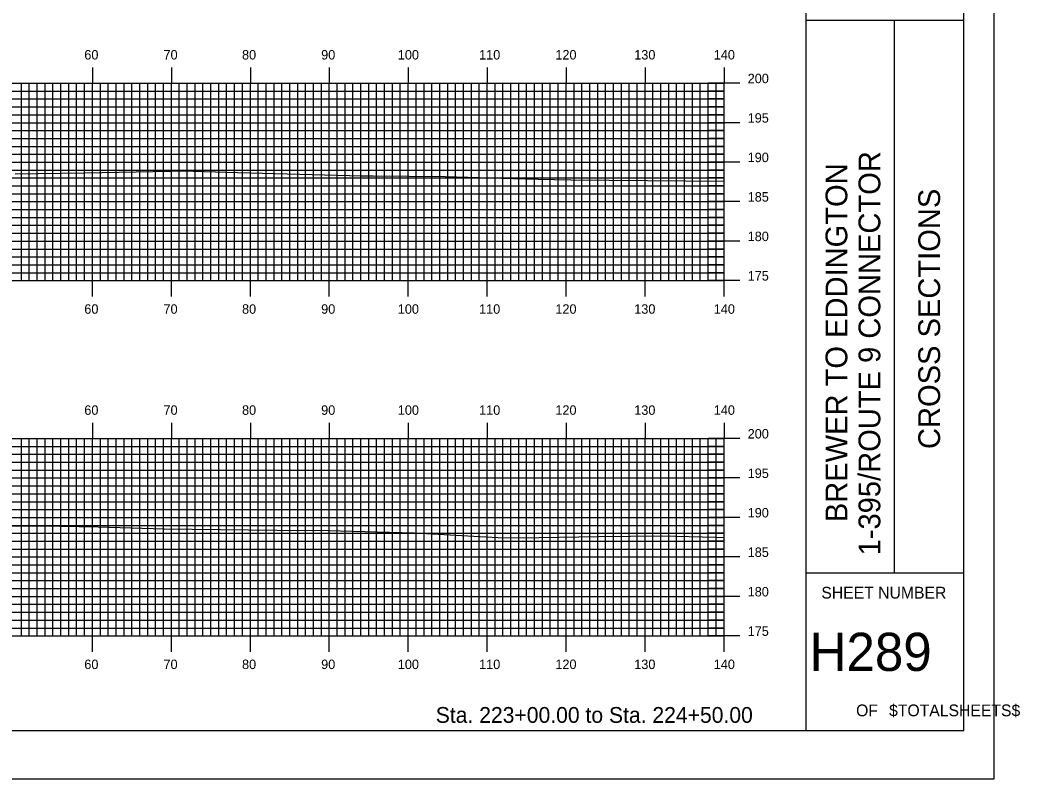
# Model space of a CAD drawing. Extents: x 1797994 to 1798337, y 442591 to 442811.
# Drawn here: x 1798210.8 to 1798337.5, y 442590.5 to 442686.7 of the extents above; entities that cross this region are included whole.
import ezdxf

# ---------------------------------------------------------------- set-up
doc = ezdxf.new("R2010")
doc.units = 0
for name, color, linetype in [('BORDER', 7, 'Continuous'), ('H_V ANNOTATION', 7, 'Continuous'), ('MAJOR', 7, 'Continuous'), ('MINOR', 7, 'Continuous'), ('PLOT BOUNDARY', 7, 'Continuous'), ('S_Roadway_Centerline', 7, 'Continuous')]:
    doc.layers.add(name, color=color, linetype=linetype)

msp = doc.modelspace()

# ---------------------------------------------------------------- linework, layer by layer
at = {"layer": 'BORDER'}
for p, q in [((1798310.36, 442596.67), (1798310.36, 442806.67)), ((1798310.36, 442686.67), (1798330.36, 442686.67)), ((1798321.54, 442616.67), (1798321.54, 442686.67)), ((1798310.36, 442616.67), (1798330.36, 442616.67))]:
    msp.add_line(p, q, dxfattribs=at)
msp.add_lwpolyline([(1798010.36, 442596.67), (1798330.36, 442596.67), (1798330.36, 442806.67), (1798010.36, 442806.67)], close=True, dxfattribs=at)
at = {"layer": 'MAJOR'}
for p, q in [((1798219.96, 442680.67), (1798219.96, 442678.67)), ((1798229.96, 442680.67), (1798229.96, 442678.67)), ((1798239.96, 442680.67), (1798239.96, 442678.67)), ((1798249.96, 442680.67), (1798249.96, 442678.67)), ((1798259.96, 442680.67), (1798259.96, 442678.67)), ((1798269.96, 442680.67), (1798269.96, 442678.67)), ((1798279.96, 442680.67), (1798279.96, 442678.67)), ((1798289.96, 442680.67), (1798289.96, 442678.67)), ((1798299.96, 442680.67), (1798299.96, 442678.67)), ((1798019.96, 442678.67), (1798299.96, 442678.67)), ((1798019.96, 442678.67), (1798299.96, 442678.67)), ((1798219.96, 442653.67), (1798219.96, 442678.67)), ((1798229.96, 442653.67), (1798229.96, 442678.67)), ((1798239.96, 442653.67), (1798239.96, 442678.67)), ((1798249.96, 442653.67), (1798249.96, 442678.67)), ((1798259.96, 442653.67), (1798259.96, 442678.67)), ((1798269.96, 442653.67), (1798269.96, 442678.67)), ((1798279.96, 442653.67), (1798279.96, 442678.67)), ((1798289.96, 442653.67), (1798289.96, 442678.67)), ((1798301.96, 442678.67), (1798297.95, 442678.67)), ((1798299.96, 442653.67), (1798299.96, 442678.67)), ((1798299.96, 442653.67), (1798299.96, 442678.67)), ((1798019.96, 442673.67), (1798299.96, 442673.67)), ((1798301.96, 442673.67), (1798297.95, 442673.67)), ((1798019.96, 442668.67), (1798299.96, 442668.67)), ((1798301.96, 442668.67), (1798297.95, 442668.67)), ((1798019.96, 442663.67), (1798299.96, 442663.67)), ((1798301.96, 442663.67), (1798297.95, 442663.67)), ((1798019.96, 442658.67), (1798299.96, 442658.67)), ((1798301.96, 442658.67), (1798297.95, 442658.67)), ((1798019.96, 442653.67), (1798299.96, 442653.67)), ((1798019.96, 442653.67), (1798299.96, 442653.67)), ((1798219.96, 442651.66), (1798219.96, 442653.67)), ((1798229.96, 442651.66), (1798229.96, 442653.67)), ((1798239.96, 442651.66), (1798239.96, 442653.67)), ((1798249.96, 442651.66), (1798249.96, 442653.67)), ((1798259.96, 442651.66), (1798259.96, 442653.67)), ((1798269.96, 442651.66), (1798269.96, 442653.67)), ((1798279.96, 442651.66), (1798279.96, 442653.67)), ((1798289.96, 442651.66), (1798289.96, 442653.67)), ((1798301.96, 442653.67), (1798297.95, 442653.67)), ((1798299.96, 442651.66), (1798299.96, 442653.67)), ((1798219.96, 442635.67), (1798219.96, 442633.67)), ((1798229.96, 442635.67), (1798229.96, 442633.67)), ((1798239.96, 442635.67), (1798239.96, 442633.67)), ((1798249.96, 442635.67), (1798249.96, 442633.67)), ((1798259.96, 442635.67), (1798259.96, 442633.67)), ((1798269.96, 442635.67), (1798269.96, 442633.67)), ((1798279.96, 442635.67), (1798279.96, 442633.67)), ((1798289.96, 442635.67), (1798289.96, 442633.67)), ((1798299.96, 442635.67), (1798299.96, 442633.67)), ((1798019.96, 442633.67), (1798299.96, 442633.67)), ((1798019.96, 442633.67), (1798299.96, 442633.67)), ((1798219.96, 442608.67), (1798219.96, 442633.67)), ((1798229.96, 442608.67), (1798229.96, 442633.67)), ((1798239.96, 442608.67), (1798239.96, 442633.67)), ((1798249.96, 442608.67), (1798249.96, 442633.67)), ((1798259.96, 442608.67), (1798259.96, 442633.67)), ((1798269.96, 442608.67), (1798269.96, 442633.67)), ((1798279.96, 442608.67), (1798279.96, 442633.67)), ((1798289.96, 442608.67), (1798289.96, 442633.67)), ((1798301.96, 442633.67), (1798297.95, 442633.67)), ((1798299.96, 442608.67), (1798299.96, 442633.67)), ((1798299.96, 442608.67), (1798299.96, 442633.67)), ((1798019.96, 442628.67), (1798299.96, 442628.67)), ((1798301.96, 442628.67), (1798297.95, 442628.67)), ((1798019.96, 442623.67), (1798299.96, 442623.67)), ((1798301.96, 442623.67), (1798297.95, 442623.67)), ((1798019.96, 442618.67), (1798299.96, 442618.67)), ((1798301.96, 442618.67), (1798297.95, 442618.67)), ((1798019.96, 442613.67), (1798299.96, 442613.67)), ((1798301.96, 442613.67), (1798297.95, 442613.67)), ((1798019.96, 442608.67), (1798299.96, 442608.67)), ((1798019.96, 442608.67), (1798299.96, 442608.67)), ((1798219.96, 442606.66), (1798219.96, 442608.67)), ((1798229.96, 442606.66), (1798229.96, 442608.67)), ((1798239.96, 442606.66), (1798239.96, 442608.67)), ((1798249.96, 442606.66), (1798249.96, 442608.67)), ((1798259.96, 442606.66), (1798259.96, 442608.67)), ((1798269.96, 442606.66), (1798269.96, 442608.67)), ((1798279.96, 442606.66), (1798279.96, 442608.67)), ((1798289.96, 442606.66), (1798289.96, 442608.67)), ((1798301.96, 442608.67), (1798297.95, 442608.67)), ((1798299.96, 442606.66), (1798299.96, 442608.67))]:
    msp.add_line(p, q, dxfattribs=at)
at = {"layer": 'MINOR'}
for p, q in [((1798210.96, 442653.67), (1798210.96, 442678.67)), ((1798211.96, 442653.67), (1798211.96, 442678.67)), ((1798212.96, 442653.67), (1798212.96, 442678.67)), ((1798213.96, 442653.67), (1798213.96, 442678.67)), ((1798214.96, 442653.67), (1798214.96, 442678.67)), ((1798215.96, 442653.67), (1798215.96, 442678.67)), ((1798216.96, 442653.67), (1798216.96, 442678.67)), ((1798217.96, 442653.67), (1798217.96, 442678.67)), ((1798218.96, 442653.67), (1798218.96, 442678.67)), ((1798220.96, 442653.67), (1798220.96, 442678.67)), ((1798221.96, 442653.67), (1798221.96, 442678.67)), ((1798222.96, 442653.67), (1798222.96, 442678.67)), ((1798223.96, 442653.67), (1798223.96, 442678.67)), ((1798224.96, 442653.67), (1798224.96, 442678.67)), ((1798225.96, 442653.67), (1798225.96, 442678.67)), ((1798226.96, 442653.67), (1798226.96, 442678.67)), ((1798227.96, 442653.67), (1798227.96, 442678.67)), ((1798228.96, 442653.67), (1798228.96, 442678.67)), ((1798230.96, 442653.67), (1798230.96, 442678.67)), ((1798231.96, 442653.67), (1798231.96, 442678.67)), ((1798232.96, 442653.67), (1798232.96, 442678.67)), ((1798233.96, 442653.67), (1798233.96, 442678.67)), ((1798234.96, 442653.67), (1798234.96, 442678.67)), ((1798235.96, 442653.67), (1798235.96, 442678.67)), ((1798236.96, 442653.67), (1798236.96, 442678.67)), ((1798237.96, 442653.67), (1798237.96, 442678.67)), ((1798238.96, 442653.67), (1798238.96, 442678.67)), ((1798240.96, 442653.67), (1798240.96, 442678.67)), ((1798241.96, 442653.67), (1798241.96, 442678.67)), ((1798242.96, 442653.67), (1798242.96, 442678.67)), ((1798243.96, 442653.67), (1798243.96, 442678.67)), ((1798244.96, 442653.67), (1798244.96, 442678.67)), ((1798245.96, 442653.67), (1798245.96, 442678.67)), ((1798246.96, 442653.67), (1798246.96, 442678.67)), ((1798247.96, 442653.67), (1798247.96, 442678.67)), ((1798248.96, 442653.67), (1798248.96, 442678.67)), ((1798250.96, 442653.67), (1798250.96, 442678.67)), ((1798251.96, 442653.67), (1798251.96, 442678.67)), ((1798252.96, 442653.67), (1798252.96, 442678.67)), ((1798253.96, 442653.67), (1798253.96, 442678.67)), ((1798254.96, 442653.67), (1798254.96, 442678.67)), ((1798255.96, 442653.67), (1798255.96, 442678.67)), ((1798256.96, 442653.67), (1798256.96, 442678.67)), ((1798257.96, 442653.67), (1798257.96, 442678.67)), ((1798258.96, 442653.67), (1798258.96, 442678.67)), ((1798260.96, 442653.67), (1798260.96, 442678.67)), ((1798261.96, 442653.67), (1798261.96, 442678.67)), ((1798262.96, 442653.67), (1798262.96, 442678.67)), ((1798263.96, 442653.67), (1798263.96, 442678.67)), ((1798264.96, 442653.67), (1798264.96, 442678.67)), ((1798265.96, 442653.67), (1798265.96, 442678.67)), ((1798266.96, 442653.67), (1798266.96, 442678.67)), ((1798267.96, 442653.67), (1798267.96, 442678.67)), ((1798268.96, 442653.67), (1798268.96, 442678.67)), ((1798270.96, 442653.67), (1798270.96, 442678.67)), ((1798271.96, 442653.67), (1798271.96, 442678.67)), ((1798272.96, 442653.67), (1798272.96, 442678.67)), ((1798273.96, 442653.67), (1798273.96, 442678.67)), ((1798274.96, 442653.67), (1798274.96, 442678.67)), ((1798275.96, 442653.67), (1798275.96, 442678.67)), ((1798276.96, 442653.67), (1798276.96, 442678.67)), ((1798277.96, 442653.67), (1798277.96, 442678.67)), ((1798278.96, 442653.67), (1798278.96, 442678.67)), ((1798280.96, 442653.67), (1798280.96, 442678.67)), ((1798281.96, 442653.67), (1798281.96, 442678.67)), ((1798282.96, 442653.67), (1798282.96, 442678.67)), ((1798283.96, 442653.67), (1798283.96, 442678.67)), ((1798284.96, 442653.67), (1798284.96, 442678.67)), ((1798285.96, 442653.67), (1798285.96, 442678.67)), ((1798286.96, 442653.67), (1798286.96, 442678.67)), ((1798287.96, 442653.67), (1798287.96, 442678.67)), ((1798288.96, 442653.67), (1798288.96, 442678.67)), ((1798290.96, 442653.67), (1798290.96, 442678.67)), ((1798291.96, 442653.67), (1798291.96, 442678.67)), ((1798292.96, 442653.67), (1798292.96, 442678.67)), ((1798293.96, 442653.67), (1798293.96, 442678.67)), ((1798294.96, 442653.67), (1798294.96, 442678.67)), ((1798295.96, 442653.67), (1798295.96, 442678.67)), ((1798296.96, 442653.67), (1798296.96, 442678.67)), ((1798297.96, 442653.67), (1798297.96, 442678.67)), ((1798298.96, 442653.67), (1798298.96, 442678.67)), ((1798019.96, 442677.67), (1798299.96, 442677.67)), ((1798299.96, 442677.67), (1798297.95, 442677.67)), ((1798019.96, 442676.67), (1798299.96, 442676.67)), ((1798299.96, 442676.67), (1798297.95, 442676.67)), ((1798019.96, 442675.67), (1798299.96, 442675.67)), ((1798299.96, 442675.67), (1798297.95, 442675.67)), ((1798019.96, 442674.67), (1798299.96, 442674.67)), ((1798299.96, 442674.67), (1798297.95, 442674.67)), ((1798019.96, 442672.67), (1798299.96, 442672.67)), ((1798299.96, 442672.67), (1798297.95, 442672.67)), ((1798019.96, 442671.67), (1798299.96, 442671.67)), ((1798299.96, 442671.67), (1798297.95, 442671.67)), ((1798019.96, 442670.67), (1798299.96, 442670.67)), ((1798299.96, 442670.67), (1798297.95, 442670.67)), ((1798019.96, 442669.67), (1798299.96, 442669.67)), ((1798299.96, 442669.67), (1798297.95, 442669.67)), ((1798019.96, 442667.67), (1798299.96, 442667.67)), ((1798299.96, 442667.67), (1798297.95, 442667.67)), ((1798019.96, 442666.67), (1798299.96, 442666.67)), ((1798299.96, 442666.67), (1798297.95, 442666.67)), ((1798019.96, 442665.67), (1798299.96, 442665.67)), ((1798019.96, 442664.67), (1798299.96, 442664.67)), ((1798299.96, 442665.67), (1798297.95, 442665.67)), ((1798299.96, 442664.67), (1798297.95, 442664.67)), ((1798019.96, 442662.67), (1798299.96, 442662.67)), ((1798299.96, 442662.67), (1798297.95, 442662.67)), ((1798019.96, 442661.67), (1798299.96, 442661.67)), ((1798299.96, 442661.67), (1798297.95, 442661.67)), ((1798019.96, 442660.67), (1798299.96, 442660.67)), ((1798019.96, 442659.67), (1798299.96, 442659.67)), ((1798299.96, 442660.67), (1798297.95, 442660.67)), ((1798299.96, 442659.67), (1798297.95, 442659.67)), ((1798019.96, 442657.67), (1798299.96, 442657.67)), ((1798299.96, 442657.67), (1798297.95, 442657.67)), ((1798019.96, 442656.67), (1798299.96, 442656.67)), ((1798299.96, 442656.67), (1798297.95, 442656.67)), ((1798019.96, 442655.67), (1798299.96, 442655.67)), ((1798019.96, 442654.67), (1798299.96, 442654.67)), ((1798299.96, 442655.67), (1798297.95, 442655.67)), ((1798299.96, 442654.67), (1798297.95, 442654.67)), ((1798210.96, 442608.67), (1798210.96, 442633.67)), ((1798211.96, 442608.67), (1798211.96, 442633.67)), ((1798212.96, 442608.67), (1798212.96, 442633.67)), ((1798213.96, 442608.67), (1798213.96, 442633.67)), ((1798214.96, 442608.67), (1798214.96, 442633.67)), ((1798215.96, 442608.67), (1798215.96, 442633.67)), ((1798216.96, 442608.67), (1798216.96, 442633.67)), ((1798217.96, 442608.67), (1798217.96, 442633.67)), ((1798218.96, 442608.67), (1798218.96, 442633.67)), ((1798220.96, 442608.67), (1798220.96, 442633.67)), ((1798221.96, 442608.67), (1798221.96, 442633.67)), ((1798222.96, 442608.67), (1798222.96, 442633.67)), ((1798223.96, 442608.67), (1798223.96, 442633.67)), ((1798224.96, 442608.67), (1798224.96, 442633.67)), ((1798225.96, 442608.67), (1798225.96, 442633.67)), ((1798226.96, 442608.67), (1798226.96, 442633.67)), ((1798227.96, 442608.67), (1798227.96, 442633.67)), ((1798228.96, 442608.67), (1798228.96, 442633.67)), ((1798230.96, 442608.67), (1798230.96, 442633.67)), ((1798231.96, 442608.67), (1798231.96, 442633.67)), ((1798232.96, 442608.67), (1798232.96, 442633.67)), ((1798233.96, 442608.67), (1798233.96, 442633.67)), ((1798234.96, 442608.67), (1798234.96, 442633.67)), ((1798235.96, 442608.67), (1798235.96, 442633.67)), ((1798236.96, 442608.67), (1798236.96, 442633.67)), ((1798237.96, 442608.67), (1798237.96, 442633.67)), ((1798238.96, 442608.67), (1798238.96, 442633.67)), ((1798240.96, 442608.67), (1798240.96, 442633.67)), ((1798241.96, 442608.67), (1798241.96, 442633.67)), ((1798242.96, 442608.67), (1798242.96, 442633.67)), ((1798243.96, 442608.67), (1798243.96, 442633.67)), ((1798244.96, 442608.67), (1798244.96, 442633.67)), ((1798245.96, 442608.67), (1798245.96, 442633.67)), ((1798246.96, 442608.67), (1798246.96, 442633.67)), ((1798247.96, 442608.67), (1798247.96, 442633.67)), ((1798248.96, 442608.67), (1798248.96, 442633.67)), ((1798250.96, 442608.67), (1798250.96, 442633.67)), ((1798251.96, 442608.67), (1798251.96, 442633.67)), ((1798252.96, 442608.67), (1798252.96, 442633.67)), ((1798253.96, 442608.67), (1798253.96, 442633.67)), ((1798254.96, 442608.67), (1798254.96, 442633.67)), ((1798255.96, 442608.67), (1798255.96, 442633.67)), ((1798256.96, 442608.67), (1798256.96, 442633.67)), ((1798257.96, 442608.67), (1798257.96, 442633.67)), ((1798258.96, 442608.67), (1798258.96, 442633.67)), ((1798260.96, 442608.67), (1798260.96, 442633.67)), ((1798261.96, 442608.67), (1798261.96, 442633.67)), ((1798262.96, 442608.67), (1798262.96, 442633.67)), ((1798263.96, 442608.67), (1798263.96, 442633.67)), ((1798264.96, 442608.67), (1798264.96, 442633.67)), ((1798265.96, 442608.67), (1798265.96, 442633.67)), ((1798266.96, 442608.67), (1798266.96, 442633.67)), ((1798267.96, 442608.67), (1798267.96, 442633.67)), ((1798268.96, 442608.67), (1798268.96, 442633.67)), ((1798270.96, 442608.67), (1798270.96, 442633.67)), ((1798271.96, 442608.67), (1798271.96, 442633.67)), ((1798272.96, 442608.67), (1798272.96, 442633.67)), ((1798273.96, 442608.67), (1798273.96, 442633.67)), ((1798274.96, 442608.67), (1798274.96, 442633.67)), ((1798275.96, 442608.67), (1798275.96, 442633.67)), ((1798276.96, 442608.67), (1798276.96, 442633.67)), ((1798277.96, 442608.67), (1798277.96, 442633.67)), ((1798278.96, 442608.67), (1798278.96, 442633.67)), ((1798280.96, 442608.67), (1798280.96, 442633.67)), ((1798281.96, 442608.67), (1798281.96, 442633.67)), ((1798282.96, 442608.67), (1798282.96, 442633.67)), ((1798283.96, 442608.67), (1798283.96, 442633.67)), ((1798284.96, 442608.67), (1798284.96, 442633.67)), ((1798285.96, 442608.67), (1798285.96, 442633.67)), ((1798286.96, 442608.67), (1798286.96, 442633.67)), ((1798287.96, 442608.67), (1798287.96, 442633.67)), ((1798288.96, 442608.67), (1798288.96, 442633.67)), ((1798290.96, 442608.67), (1798290.96, 442633.67)), ((1798291.96, 442608.67), (1798291.96, 442633.67)), ((1798292.96, 442608.67), (1798292.96, 442633.67)), ((1798293.96, 442608.67), (1798293.96, 442633.67)), ((1798294.96, 442608.67), (1798294.96, 442633.67)), ((1798295.96, 442608.67), (1798295.96, 442633.67)), ((1798296.96, 442608.67), (1798296.96, 442633.67)), ((1798297.96, 442608.67), (1798297.96, 442633.67)), ((1798298.96, 442608.67), (1798298.96, 442633.67)), ((1798019.96, 442632.67), (1798299.96, 442632.67)), ((1798299.96, 442632.67), (1798297.95, 442632.67)), ((1798019.96, 442631.67), (1798299.96, 442631.67)), ((1798019.96, 442630.67), (1798299.96, 442630.67)), ((1798299.96, 442631.67), (1798297.95, 442631.67)), ((1798299.96, 442630.67), (1798297.95, 442630.67)), ((1798019.96, 442629.67), (1798299.96, 442629.67)), ((1798299.96, 442629.67), (1798297.95, 442629.67)), ((1798019.96, 442627.67), (1798299.96, 442627.67)), ((1798019.96, 442626.67), (1798299.96, 442626.67)), ((1798299.96, 442627.67), (1798297.95, 442627.67)), ((1798299.96, 442626.67), (1798297.95, 442626.67)), ((1798019.96, 442625.67), (1798299.96, 442625.67)), ((1798299.96, 442625.67), (1798297.95, 442625.67)), ((1798019.96, 442624.67), (1798299.96, 442624.67)), ((1798299.96, 442624.67), (1798297.95, 442624.67)), ((1798019.96, 442622.67), (1798299.96, 442622.67)), ((1798019.96, 442621.67), (1798299.96, 442621.67)), ((1798299.96, 442622.67), (1798297.95, 442622.67)), ((1798299.96, 442621.67), (1798297.95, 442621.67)), ((1798019.96, 442620.67), (1798299.96, 442620.67)), ((1798299.96, 442620.67), (1798297.95, 442620.67)), ((1798019.96, 442619.67), (1798299.96, 442619.67)), ((1798299.96, 442619.67), (1798297.95, 442619.67)), ((1798019.96, 442617.67), (1798299.96, 442617.67)), ((1798019.96, 442616.67), (1798299.96, 442616.67)), ((1798299.96, 442617.67), (1798297.95, 442617.67)), ((1798299.96, 442616.67), (1798297.95, 442616.67)), ((1798019.96, 442615.67), (1798299.96, 442615.67)), ((1798299.96, 442615.67), (1798297.95, 442615.67)), ((1798019.96, 442614.67), (1798299.96, 442614.67)), ((1798299.96, 442614.67), (1798297.95, 442614.67)), ((1798019.96, 442612.67), (1798299.96, 442612.67)), ((1798019.96, 442611.67), (1798299.96, 442611.67)), ((1798299.96, 442612.67), (1798297.95, 442612.67)), ((1798299.96, 442611.67), (1798297.95, 442611.67)), ((1798019.96, 442610.67), (1798299.96, 442610.67)), ((1798299.96, 442610.67), (1798297.95, 442610.67)), ((1798019.96, 442609.67), (1798299.96, 442609.67)), ((1798299.96, 442609.67), (1798297.95, 442609.67))]:
    msp.add_line(p, q, dxfattribs=at)
at = {"layer": 'PLOT BOUNDARY'}
msp.add_lwpolyline([(1797994.17, 442590.55), (1798334.17, 442590.55), (1798334.17, 442810.55), (1797994.17, 442810.55)], close=True, dxfattribs=at)
at = {"layer": 'S_Roadway_Centerline'}
for points in [[(1798210.16, 442667.18), (1798218.97, 442667.3), (1798229.86, 442667.54), (1798230.6, 442667.57), (1798231.32, 442667.59), (1798238.34, 442667.37), (1798252.51, 442666.96), (1798253.97, 442666.95), (1798255.56, 442666.94), (1798264.66, 442666.85), (1798273.19, 442666.58), (1798276.43, 442666.53), (1798280.55, 442666.43), (1798299.96, 442666.25)], [(1798207.69, 442622.6), (1798213.43, 442622.63), (1798220.69, 442622.47), (1798229.04, 442622.24), (1798246.87, 442622.04), (1798247.79, 442622.05), (1798249.82, 442622.01), (1798260.73, 442621.73), (1798271.29, 442621.14), (1798274.02, 442621.09), (1798284.12, 442621.26), (1798292.12, 442621.36), (1798298.94, 442621.18), (1798299.96, 442621.14)]]:
    msp.add_lwpolyline(points, dxfattribs=at)

# ---------------------------------------------------------------- texts
at = {"layer": 'BORDER'}
for s, p in [('1-395/ROUTE 9 CONNECTOR', (1798319.76, 442618.87)), ('BREWER TO EDDINGTON', (1798315.58, 442623.07)), ('CROSS SECTIONS', (1798327.33, 442632.34))]:
    msp.add_text(s, height=2.7557, rotation=90, dxfattribs=at).set_placement(p)
for s, height, p in [('SHEET NUMBER', 1.4905, (1798312.29, 442613.4)), ('H289', 4.839, (1798310.8, 442604.23)), ('$TOTALSHEETS$', 1.4905, (1798320.87, 442598.49)), ('OF', 1.491, (1798316.69, 442598.49))]:
    msp.add_text(s, height=height, dxfattribs=at).set_placement(p)
at = {"layer": 'H_V ANNOTATION'}
for s, height, p in [('60', 1.2, (1798218.93, 442681.67)), ('70', 1.2, (1798228.96, 442681.67)), ('80', 1.2, (1798238.91, 442681.67)), ('90', 1.2, (1798248.93, 442681.67)), ('100', 1.2, (1798258.64, 442681.67)), ('110', 1.2, (1798268.94, 442681.67)), ('120', 1.2, (1798278.6, 442681.67)), ('130', 1.2, (1798288.59, 442681.67)), ('140', 1.2, (1798298.66, 442681.67)), ('200', 1.2, (1798302.96, 442678.67)), ('195', 1.2, (1798302.96, 442673.67)), ('190', 1.2, (1798302.96, 442668.67)), ('185', 1.2, (1798302.96, 442663.67)), ('180', 1.2, (1798302.96, 442658.67)), ('175', 1.2, (1798302.96, 442653.67)), ('60', 1.2, (1798218.93, 442649.47)), ('70', 1.2, (1798228.96, 442649.47)), ('80', 1.2, (1798238.91, 442649.47)), ('90', 1.2, (1798248.93, 442649.47)), ('100', 1.2, (1798258.64, 442649.47)), ('110', 1.2, (1798268.94, 442649.47)), ('120', 1.2, (1798278.6, 442649.47)), ('130', 1.2, (1798288.59, 442649.47)), ('140', 1.2, (1798298.66, 442649.47)), ('60', 1.2, (1798218.93, 442636.67)), ('70', 1.2, (1798228.96, 442636.67)), ('80', 1.2, (1798238.91, 442636.67)), ('90', 1.2, (1798248.93, 442636.67)), ('100', 1.2, (1798258.64, 442636.67)), ('110', 1.2, (1798268.94, 442636.67)), ('120', 1.2, (1798278.6, 442636.67)), ('130', 1.2, (1798288.59, 442636.67)), ('140', 1.2, (1798298.66, 442636.67)), ('200', 1.2, (1798302.96, 442633.67)), ('195', 1.2, (1798302.96, 442628.67)), ('190', 1.2, (1798302.96, 442623.67)), ('185', 1.2, (1798302.96, 442618.67)), ('180', 1.2, (1798302.96, 442613.67)), ('175', 1.2, (1798302.96, 442608.67)), ('60', 1.2, (1798218.93, 442604.47)), ('70', 1.2, (1798228.96, 442604.47)), ('80', 1.2, (1798238.91, 442604.47)), ('90', 1.2, (1798248.93, 442604.47)), ('100', 1.2, (1798258.64, 442604.47)), ('110', 1.2, (1798268.94, 442604.47)), ('120', 1.2, (1798278.6, 442604.47)), ('130', 1.2, (1798288.59, 442604.47)), ('140', 1.2, (1798298.66, 442604.47)), ('Sta. 223+00.00 to Sta. 224+50.00', 2.0004, (1798263.45, 442597.66))]:
    msp.add_text(s, height=height, dxfattribs=at).set_placement(p)

doc.saveas('drawing.dxf')
